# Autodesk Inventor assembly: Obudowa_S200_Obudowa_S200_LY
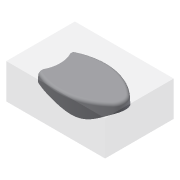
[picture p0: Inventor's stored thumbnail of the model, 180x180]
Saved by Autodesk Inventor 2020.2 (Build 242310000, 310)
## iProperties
Created: 2015-02
Part Number: Obudowa_S200_Obudowa_S200_LY
Document SubType Name: Assembly
Designer: F.Stasiak
Catalog Web Link: www.expertbooks.pl
Manager: www.cadconsulting.pl
Company: Fabian Stasiak CAD Consulting
Author: F.Stasiak
Subject: Zbiór ćwiczeń. Autodesk Inventor 2020. Kurs Professional
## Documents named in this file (2)
- C:\2020_Kurs_Professional\R6 Formy\Komponenty\Obudowa_S200_Obudowa_S200_LY.iam
- C:\2020_Kurs_Professional\R6 Formy\Komponenty\Obudowa_S200_Obudowa_S200_PZ.iam
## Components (1 placed, 1 different names)
1. Obudowa_S200_Obudowa_S200_PZ:1 [sub-assembly] — Równoległy:1, Równoległy:2, Równoległy:3
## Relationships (3: Flush 3)
- Równoległy:1 [Flush]: Obudowa_S200_Obudowa_S200_PZ:1
- Równoległy:2 [Flush]: Obudowa_S200_Obudowa_S200_PZ:1
- Równoległy:3 [Flush]: Obudowa_S200_Obudowa_S200_PZ:1
